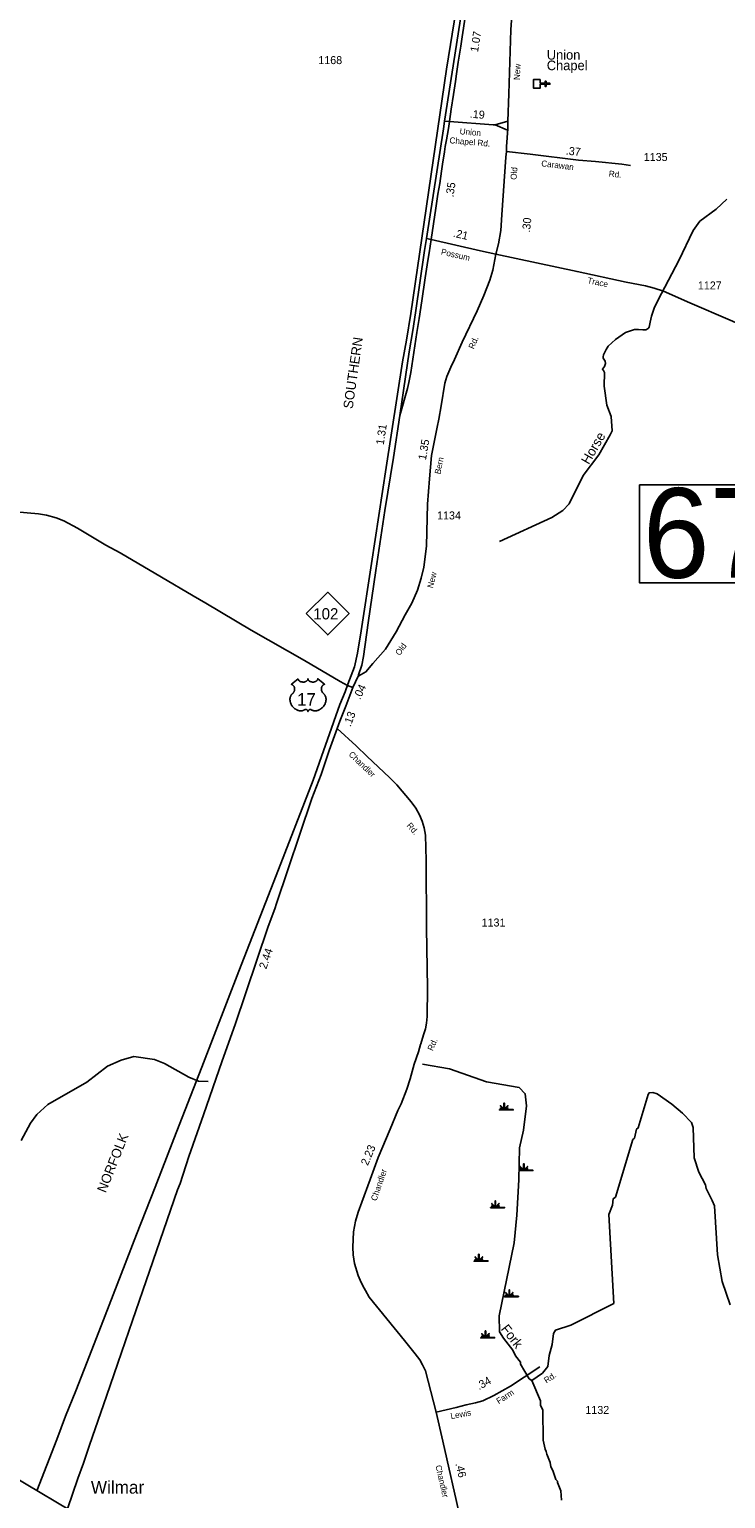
# Model space of a CAD drawing. Extents: x 2532689 to 2764727, y 536648 to 732970.
# Drawn here: x 2552614 to 2563477, y 604102 to 627049 of the extents above; entities that cross this region are included whole.
import ezdxf

# ---------------------------------------------------------------- set-up
doc = ezdxf.new("R2010")
doc.units = 0
for name, color, linetype in [('Exist Boundary Political CountyLine', 7, 'Continuous'), ('Exist Civil Demographics Community Label', 7, 'Continuous'), ('Exist Cultural Church CELL', 7, 'Continuous'), ('Exist Cultural Church Label', 7, 'Continuous'), ('Exist Hydrographic Creek Single Shore', 7, 'Continuous'), ('Exist Hydrographic Creek Single Shore Label', 7, 'Continuous'), ('Exist Hydrographic Swamp CELL', 7, 'Continuous'), ('Exist Railroad Mainline', 7, 'Continuous'), ('Exist Railroad Mainline Label', 7, 'Continuous'), ('Exist Road Primary NC Attributed', 7, 'Continuous'), ('Exist Road Primary NC Shield CELL', 7, 'Continuous'), ('Exist Road Primary NC Shield Number Label', 7, 'Continuous'), ('Exist Road Primary US Attributed', 7, 'Continuous'), ('Exist Road Primary US Divided Attributed', 7, 'Continuous'), ('Exist Road Primary US Mileage Hundredths English Label', 7, 'Continuous'), ('Exist Road Primary US Shield CELL', 7, 'Continuous'), ('Exist Road Primary US Shield Number Label', 7, 'Continuous'), ('Exist Road Secondary Mileage Hundredths English Label', 7, 'Continuous'), ('Exist Road Secondary Structure Standard Bridge Number Label', 7, 'Continuous'), ('Exist Road Secondary Type 20 Attributed', 7, 'Continuous'), ('Exist Road Secondary Type 51 Attributed', 7, 'Continuous'), ('Exist Road Secondary Type 51 Divided Attributed', 7, 'Continuous'), ('Exist Road Secondary Type 51 Label', 7, 'Continuous'), ('Exist Road Secondary Type 51 Number Label', 7, 'Continuous')]:
    doc.layers.add(name, color=color, linetype=linetype)

msp = doc.modelspace()

# ---------------------------------------------------------------- linework, layer by layer
at = {"layer": 'Exist Boundary Political CountyLine'}
msp.add_lwpolyline([(2539489, 612112), (2541484, 610924), (2543090, 609968), (2546865, 607719), (2548776, 606581), (2551142, 605172), (2553489, 603774), (2555345, 602668), (2557351, 601473), (2559512, 600187), (2561378, 599075), (2566102, 596262), (2569405, 594294), (2586179, 584303), (2593549, 579914), (2608947, 570743), (2617220, 563503), (2625601, 556169), (2628092, 553990)], dxfattribs=at)
at = {"layer": 'Exist Cultural Church CELL'}
msp.add_lwpolyline([(2560584, 626264), (2560584, 626207), (2560661, 626207), (2560661, 626239), (2560677, 626239), (2560677, 626207), (2560737, 626207), (2560737, 626191), (2560677, 626191), (2560677, 626159), (2560661, 626159), (2560661, 626191), (2560584, 626191), (2560584, 626133), (2560478, 626133), (2560478, 626264)], close=True, dxfattribs=at)
at = {"layer": 'Exist Hydrographic Creek Single Shore'}
for points in [[(2559949, 619049), (2560766, 619424), (2560939, 619536), (2561037, 619638), (2561253, 620083), (2561498, 620405), (2561674, 620718), (2561706, 620778), (2561694, 621001), (2561623, 621182), (2561584, 621476), (2561585, 621691), (2561574, 621719), (2561555, 621744), (2561587, 621782), (2561601, 621830), (2561598, 621865), (2561566, 621912), (2561569, 621937), (2561571, 621964), (2561614, 622048), (2561645, 622103), (2561759, 622207), (2561917, 622315), (2562055, 622360), (2562118, 622363), (2562184, 622356), (2562232, 622358), (2562268, 622377), (2562282, 622396), (2562302, 622477), (2562319, 622570), (2562366, 622713), (2562477, 622924), (2562746, 623440), (2562970, 623909), (2563076, 624054), (2563330, 624242), (2563494, 624396)], [(2552488, 609696), (2552632, 609965), (2552730, 610100), (2552902, 610255), (2553512, 610608), (2553833, 610854), (2554047, 610951), (2554246, 611005), (2554564, 610959), (2554723, 610896), (2555103, 610685), (2555253, 610622), (2555403, 610615)], [(2560456, 605944), (2560413, 605975), (2560276, 606199), (2560275, 606232), (2560198, 606331), (2560155, 606421), (2560009, 606609), (2559949, 606708), (2559944, 606957), (2560180, 608096), (2560222, 608531), (2560253, 609081), (2560260, 609580), (2560321, 609858), (2560372, 610235), (2560351, 610424), (2560258, 610522), (2559748, 610613), (2559169, 610816), (2558750, 610885)], [(2560456, 605944), (2560620, 606062), (2560701, 606164), (2560723, 606339), (2560770, 606508), (2560791, 606683), (2560824, 606734), (2561064, 606812), (2561732, 607151), (2561655, 608540), (2561710, 608683), (2561725, 608786), (2561758, 608810), (2562032, 609708), (2562057, 609732), (2562087, 609874), (2562112, 609891), (2562268, 610413), (2562284, 610437), (2562343, 610446), (2562410, 610422), (2562638, 610261), (2562807, 610123), (2562944, 609974), (2562970, 609900), (2562988, 609425), (2563059, 609201), (2563163, 609005), (2563172, 608946), (2563267, 608756), (2563302, 608672), (2563351, 607909), (2563425, 607492), (2563549, 607129)], [(2560917, 604078), (2560906, 604225), (2560853, 604351), (2560853, 604374), (2560827, 604400), (2560783, 604542), (2560749, 604600), (2560739, 604665), (2560686, 604798), (2560677, 604840), (2560660, 604872), (2560632, 605012), (2560623, 605481), (2560588, 605562), (2560587, 605628), (2560456, 605944)]]:
    msp.add_lwpolyline(points, dxfattribs=at)
at = {"layer": 'Exist Hydrographic Swamp CELL'}
for points in [[(2559947, 610179), (2559999, 610179), (2560001, 610183), (2559963, 610198), (2559966, 610203), (2560004, 610187), (2560005, 610190), (2559961, 610235), (2559966, 610240), (2560011, 610194), (2560018, 610197), (2560018, 610280), (2560025, 610280), (2560025, 610197), (2560031, 610194), (2560077, 610240), (2560082, 610235), (2560037, 610190), (2560039, 610187), (2560080, 610205), (2560083, 610200), (2560042, 610182), (2560043, 610179), (2560164, 610179), (2560164, 610172), (2559947, 610172)], [(2560254, 609231), (2560306, 609231), (2560308, 609234), (2560270, 609249), (2560273, 609255), (2560311, 609239), (2560312, 609242), (2560268, 609286), (2560273, 609291), (2560318, 609246), (2560325, 609248), (2560325, 609331), (2560332, 609331), (2560332, 609248), (2560338, 609246), (2560384, 609291), (2560389, 609286), (2560344, 609242), (2560346, 609238), (2560387, 609257), (2560390, 609252), (2560349, 609234), (2560350, 609231), (2560471, 609231), (2560471, 609224), (2560254, 609224)], [(2559810, 608651), (2559863, 608651), (2559865, 608655), (2559827, 608669), (2559830, 608675), (2559867, 608659), (2559869, 608662), (2559825, 608706), (2559830, 608711), (2559875, 608666), (2559881, 608668), (2559881, 608751), (2559889, 608751), (2559889, 608668), (2559895, 608666), (2559940, 608711), (2559945, 608706), (2559901, 608662), (2559903, 608658), (2559944, 608677), (2559946, 608672), (2559905, 608654), (2559907, 608651), (2560028, 608651), (2560028, 608644), (2559810, 608644)], [(2559552, 607817), (2559604, 607817), (2559606, 607821), (2559568, 607836), (2559571, 607841), (2559609, 607825), (2559610, 607828), (2559566, 607872), (2559571, 607878), (2559616, 607832), (2559623, 607834), (2559623, 607918), (2559630, 607918), (2559630, 607834), (2559636, 607832), (2559682, 607878), (2559687, 607872), (2559642, 607828), (2559644, 607824), (2559685, 607843), (2559688, 607838), (2559647, 607820), (2559648, 607817), (2559769, 607817), (2559769, 607810), (2559552, 607810)], [(2560027, 607261), (2560080, 607261), (2560082, 607264), (2560044, 607279), (2560047, 607284), (2560084, 607269), (2560086, 607272), (2560042, 607316), (2560047, 607321), (2560092, 607276), (2560098, 607278), (2560098, 607361), (2560106, 607361), (2560105, 607278), (2560112, 607276), (2560157, 607321), (2560162, 607316), (2560118, 607272), (2560120, 607268), (2560161, 607287), (2560163, 607282), (2560122, 607264), (2560124, 607261), (2560245, 607261), (2560245, 607254), (2560027, 607254)], [(2559656, 606619), (2559708, 606619), (2559710, 606623), (2559672, 606638), (2559675, 606643), (2559713, 606627), (2559714, 606630), (2559670, 606675), (2559675, 606680), (2559720, 606634), (2559727, 606637), (2559727, 606720), (2559734, 606720), (2559734, 606637), (2559740, 606634), (2559785, 606680), (2559791, 606675), (2559746, 606630), (2559748, 606627), (2559789, 606645), (2559792, 606640), (2559751, 606622), (2559752, 606619), (2559873, 606619), (2559873, 606612), (2559656, 606612)]]:
    msp.add_lwpolyline(points, close=True, dxfattribs=at)
at = {"layer": 'Exist Railroad Mainline'}
msp.add_lwpolyline([(2552731, 604225), (2553044, 605026), (2553179, 605388), (2553340, 605787), (2553468, 606119), (2553735, 606802), (2554045, 607606), (2554283, 608226), (2554578, 608968), (2554868, 609723), (2555303, 610839), (2555882, 612338), (2556466, 613836), (2557041, 615325), (2557457, 616503), (2557539, 616700), (2557584, 616824), (2557685, 617095), (2557735, 617306), (2557793, 617657), (2557953, 618705), (2558182, 620206), (2558438, 621856), (2558498, 622195), (2558566, 622610), (2559124, 626429), (2559455, 628488)], dxfattribs=at)
at = {"layer": 'Exist Road Primary NC Attributed'}
for points in [[(2552403, 619515), (2552756, 619481), (2552879, 619463), (2553034, 619418), (2553152, 619371), (2553365, 619260), (2553808, 618994), (2554030, 618871), (2554675, 618493), (2555170, 618202), (2555369, 618088), (2556075, 617667), (2556905, 617191), (2557461, 616863), (2557575, 616800)], [(2557575, 616800), (2557660, 616769)]]:
    msp.add_lwpolyline(points, dxfattribs=at)
at = {"layer": 'Exist Road Primary NC Shield CELL'}
msp.add_lwpolyline([(2556935, 617924), (2557268, 618257), (2557601, 617924), (2557268, 617591)], close=True, dxfattribs=at)
at = {"layer": 'Exist Road Primary US Attributed'}
msp.add_line((2557660, 616769), (2557745, 616949), dxfattribs=at)
for points in [[(2557745, 616949), (2557751, 616970), (2557799, 617119), (2557828, 617253), (2557898, 617778), (2558020, 618596), (2558162, 619533), (2558293, 620364), (2558395, 621018), (2558395, 621018)], [(2557415, 616128), (2557460, 616244), (2557549, 616478), (2557660, 616769)], [(2553208, 603941), (2553370, 604418), (2553458, 604656), (2553552, 604935), (2553816, 605700), (2553995, 606216), (2554221, 606881), (2554487, 607652), (2554923, 608925), (2554966, 609023), (2555104, 609444), (2555329, 610097), (2555622, 610940), (2555823, 611508), (2556335, 613022), (2556447, 613331), (2556464, 613382), (2557023, 615034), (2557168, 615414), (2557290, 615784), (2557415, 616128)]]:
    msp.add_lwpolyline(points, dxfattribs=at)
at = {"layer": 'Exist Road Primary US Divided Attributed'}
for points in [[(2559093, 625618), (2559329, 627145), (2559682, 629461), (2559748, 629889), (2559902, 630931), (2559956, 631259)], [(2559169, 625612), (2559193, 625805), (2559230, 626033), (2559260, 626236), (2559278, 626353), (2559306, 626537), (2559330, 626695), (2559345, 626787), (2559367, 626935), (2559413, 627238)], [(2558808, 623783), (2559074, 625498), (2559093, 625618)], [(2558882, 623768), (2558918, 624011), (2558956, 624256), (2558989, 624475), (2559017, 624643), (2559046, 624836), (2559060, 624943), (2559091, 625135), (2559103, 625222), (2559121, 625325), (2559152, 625499), (2559169, 625612)], [(2558395, 621018), (2558538, 622013), (2558596, 622344), (2558636, 622624), (2558781, 623596), (2558808, 623783)], [(2558395, 621018), (2558514, 621442), (2558535, 621536), (2558566, 621692), (2558595, 621898), (2558627, 622107), (2558659, 622314), (2558695, 622536), (2558737, 622812), (2558790, 623167), (2558832, 623439), (2558850, 623559), (2558882, 623768)]]:
    msp.add_lwpolyline(points, dxfattribs=at)
at = {"layer": 'Exist Road Primary US Shield CELL'}
msp.add_lwpolyline([(2556809, 616906), (2556809, 616902), (2556810, 616896), (2556811, 616894), (2556814, 616889), (2556818, 616882), (2556823, 616876), (2556830, 616871), (2556834, 616869), (2556841, 616865), (2556849, 616861), (2556858, 616859), (2556868, 616857), (2556878, 616856), (2556888, 616855), (2556899, 616856), (2556911, 616858), (2556917, 616860), (2556923, 616862), (2556929, 616864), (2556935, 616868), (2556940, 616871), (2556944, 616874), (2556950, 616879), (2556954, 616885), (2556956, 616888), (2556958, 616891), (2556960, 616898), (2556961, 616900), (2556961, 616906), (2556961, 616901), (2556962, 616898), (2556963, 616895), (2556964, 616892), (2556966, 616887), (2556969, 616884), (2556973, 616878), (2556976, 616875), (2556979, 616873), (2556986, 616868), (2556995, 616864), (2556999, 616862), (2557003, 616861), (2557009, 616859), (2557014, 616858), (2557020, 616857), (2557025, 616856), (2557031, 616855), (2557036, 616855), (2557042, 616855), (2557047, 616856), (2557052, 616856), (2557058, 616857), (2557063, 616858), (2557070, 616860), (2557075, 616862), (2557081, 616864), (2557087, 616868), (2557092, 616871), (2557096, 616874), (2557101, 616879), (2557105, 616884), (2557108, 616887), (2557110, 616891), (2557111, 616895), (2557113, 616899), (2557113, 616903), (2557113, 616906), (2557219, 616822), (2557217, 616821), (2557211, 616818), (2557207, 616815), (2557199, 616810), (2557196, 616807), (2557193, 616804), (2557190, 616801), (2557188, 616798), (2557184, 616794), (2557182, 616790), (2557179, 616785), (2557177, 616781), (2557174, 616772), (2557172, 616767), (2557171, 616762), (2557170, 616753), (2557170, 616748), (2557170, 616744), (2557170, 616739), (2557170, 616735), (2557171, 616730), (2557172, 616726), (2557173, 616721), (2557175, 616715), (2557177, 616709), (2557182, 616700), (2557188, 616690), (2557193, 616685), (2557197, 616681), (2557204, 616675), (2557207, 616672), (2557212, 616668), (2557218, 616660), (2557221, 616657), (2557224, 616652), (2557226, 616648), (2557229, 616644), (2557231, 616640), (2557234, 616631), (2557237, 616622), (2557238, 616617), (2557240, 616607), (2557241, 616602), (2557242, 616591), (2557242, 616579), (2557241, 616567), (2557239, 616554), (2557237, 616546), (2557234, 616536), (2557231, 616528), (2557227, 616516), (2557222, 616507), (2557217, 616497), (2557213, 616490), (2557208, 616484), (2557203, 616476), (2557196, 616468), (2557188, 616459), (2557182, 616453), (2557174, 616446), (2557169, 616441), (2557162, 616436), (2557152, 616430), (2557142, 616424), (2557134, 616420), (2557127, 616417), (2557117, 616413), (2557102, 616409), (2557096, 616408), (2557089, 616407), (2557083, 616406), (2557077, 616405), (2557068, 616405), (2557060, 616406), (2557052, 616407), (2557044, 616409), (2557036, 616411), (2557028, 616414), (2557020, 616418), (2557007, 616427), (2557003, 616429), (2557001, 616429), (2556996, 616429), (2556991, 616428), (2556986, 616426), (2556984, 616425), (2556980, 616422), (2556977, 616420), (2556973, 616416), (2556970, 616414), (2556969, 616411), (2556965, 616405), (2556964, 616403), (2556962, 616399), (2556961, 616394), (2556959, 616401), (2556957, 616405), (2556955, 616409), (2556953, 616412), (2556949, 616416), (2556946, 616419), (2556942, 616423), (2556937, 616425), (2556934, 616427), (2556931, 616428), (2556927, 616429), (2556924, 616429), (2556921, 616429), (2556918, 616429), (2556913, 616425), (2556908, 616422), (2556903, 616419), (2556898, 616416), (2556893, 616414), (2556888, 616412), (2556882, 616410), (2556875, 616408), (2556869, 616407), (2556863, 616406), (2556857, 616405), (2556851, 616405), (2556845, 616405), (2556839, 616406), (2556833, 616406), (2556825, 616407), (2556818, 616409), (2556811, 616411), (2556804, 616413), (2556796, 616416), (2556786, 616420), (2556780, 616424), (2556769, 616430), (2556757, 616438), (2556747, 616446), (2556740, 616452), (2556730, 616462), (2556724, 616469), (2556715, 616481), (2556709, 616490), (2556705, 616496), (2556700, 616507), (2556697, 616513), (2556693, 616522), (2556689, 616531), (2556687, 616539), (2556685, 616544), (2556683, 616554), (2556682, 616560), (2556681, 616569), (2556680, 616578), (2556680, 616587), (2556680, 616594), (2556681, 616602), (2556683, 616611), (2556684, 616619), (2556686, 616624), (2556688, 616631), (2556691, 616638), (2556695, 616645), (2556698, 616651), (2556702, 616657), (2556706, 616663), (2556712, 616669), (2556717, 616674), (2556722, 616678), (2556729, 616684), (2556732, 616688), (2556736, 616693), (2556739, 616698), (2556741, 616702), (2556744, 616708), (2556746, 616713), (2556749, 616720), (2556750, 616725), (2556751, 616731), (2556752, 616738), (2556752, 616745), (2556752, 616751), (2556751, 616759), (2556750, 616766), (2556748, 616772), (2556746, 616779), (2556743, 616784), (2556739, 616791), (2556735, 616798), (2556730, 616803), (2556725, 616808), (2556721, 616811), (2556717, 616814), (2556711, 616817), (2556706, 616820), (2556703, 616821)], close=True, dxfattribs=at)
at = {"layer": 'Exist Road Secondary Structure Standard Bridge Number Label'}
msp.add_lwpolyline([(2562135, 619935), (2564712, 619935), (2564712, 618405), (2562135, 618405)], close=True, dxfattribs=at)
at = {"layer": 'Exist Road Secondary Type 20 Attributed'}
msp.add_lwpolyline([(2558960, 605451), (2559274, 605527), (2559428, 605568), (2559577, 605595), (2559688, 605631), (2559859, 605713), (2560120, 605858), (2560333, 605998), (2560580, 606161)], dxfattribs=at)
at = {"layer": 'Exist Road Secondary Type 51 Attributed'}
msp.add_line((2558882, 623768), (2558808, 623783), dxfattribs=at)
for points in [[(2560081, 625615), (2560094, 626043), (2560126, 627043), (2560145, 627337), (2560170, 627959), (2560167, 628059), (2560153, 628147), (2560137, 628342), (2560128, 628438), (2560113, 628699), (2560124, 628814), (2560140, 628994), (2560151, 629098), (2560181, 629417), (2560177, 629474), (2560222, 629909), (2560261, 630550), (2560337, 630908), (2560369, 631077), (2560387, 631172)], [(2559093, 625618), (2559169, 625612)], [(2559169, 625612), (2559851, 625559), (2559879, 625557), (2559881, 625556)], [(2560078, 625498), (2560081, 625615)], [(2560056, 625144), (2560060, 625219), (2560078, 625498)], [(2559890, 623538), (2559936, 623698), (2559969, 623907), (2559987, 624152), (2560048, 625055), (2560056, 625144)], [(2560056, 625144), (2560430, 625098), (2561184, 625005), (2561448, 624985), (2561859, 624942), (2561991, 624923)], [(2559890, 623538), (2559652, 623593), (2558882, 623768)], [(2557745, 616949), (2557789, 616972), (2557864, 617014), (2557975, 617146), (2558170, 617369), (2558339, 617639), (2558478, 617903), (2558579, 618090), (2558667, 618290), (2558727, 618477), (2558770, 618652), (2558785, 618768), (2558810, 618982), (2558827, 619636), (2558856, 620031), (2558889, 620393), (2558975, 620835), (2559001, 620959), (2559037, 621169), (2559098, 621524), (2559127, 621628), (2559188, 621776), (2559246, 621895), (2559368, 622163), (2559601, 622651), (2559704, 622891), (2559798, 623134), (2559843, 623289), (2559890, 623538)], [(2568438, 621427), (2567962, 621436), (2567357, 621448), (2566914, 621452), (2566419, 621460), (2566075, 621474), (2565968, 621487), (2565900, 621502), (2565716, 621565), (2565507, 621652), (2564415, 622129), (2563547, 622505), (2562917, 622777), (2562508, 622960), (2562364, 623007), (2562228, 623042), (2561924, 623103), (2561159, 623266), (2559890, 623538)], [(2557415, 616128), (2557714, 615857), (2557886, 615693), (2558234, 615365), (2558348, 615248), (2558572, 614986), (2558643, 614885), (2558702, 614780), (2558742, 614684), (2558775, 614581), (2558793, 614464), (2558805, 614069), (2558811, 613018), (2558825, 612073), (2558819, 611630), (2558808, 611528), (2558792, 611440), (2558764, 611346), (2558720, 611206), (2558714, 611192), (2558683, 611081), (2558619, 610888), (2558553, 610657), (2558502, 610498), (2558413, 610267), (2558364, 610162), (2558244, 609870), (2558054, 609427), (2557933, 609086), (2557802, 608733), (2557743, 608573), (2557704, 608437), (2557672, 608266), (2557660, 608030), (2557666, 607909), (2557688, 607776), (2557744, 607585), (2557790, 607478), (2557837, 607389), (2557858, 607353), (2557917, 607248), (2558466, 606571), (2558633, 606363), (2558704, 606270), (2558750, 606192), (2558793, 606095), (2558960, 605451)], [(2558960, 605451), (2559065, 604997), (2559339, 603782), (2559361, 603566), (2559351, 603384), (2559330, 603080)]]:
    msp.add_lwpolyline(points, dxfattribs=at)
at = {"layer": 'Exist Road Secondary Type 51 Divided Attributed'}
msp.add_line((2559881, 625556), (2560081, 625615), dxfattribs=at)
msp.add_lwpolyline([(2559881, 625556), (2560076, 625473)], dxfattribs=at)

# ---------------------------------------------------------------- texts
at = {"layer": 'Exist Civil Demographics Community Label'}
msp.add_text('Wilmar', height=200, dxfattribs=at).set_placement((2553573, 604179))
at = {"layer": 'Exist Cultural Church Label'}
for s, p in [('Union', (2560687, 626577)), ('Chapel', (2560687, 626412))]:
    msp.add_text(s, height=150, dxfattribs=at).set_placement(p)
at = {"layer": 'Exist Hydrographic Creek Single Shore Label'}
for s, rotation, p in [('Horse', 60.0294, (2561343, 620242)), ('Fork', 307.8577, (2559962, 606749))]:
    msp.add_text(s, height=150, rotation=rotation, dxfattribs=at).set_placement(p)
at = {"layer": 'Exist Railroad Mainline Label'}
for s, rotation, p in [('SOUTHERN', 81.8619, (2557658, 621117)), ('NORFOLK', 68.2688, (2553804, 608868))]:
    msp.add_text(s, height=150, rotation=rotation, dxfattribs=at).set_placement(p)
at = {"layer": 'Exist Road Primary NC Shield Number Label'}
msp.add_text('102', height=175, dxfattribs=at).set_placement((2557044, 617834))
at = {"layer": 'Exist Road Primary US Mileage Hundredths English Label'}
for s, rotation, p in [('1.07', 80.7675, (2559613, 626688)), ('.35', 81.202, (2559229, 624423)), ('1.31', 81.2511, (2558142, 620553)), ('.04', 64.727, (2557774, 616572)), ('.13', 69.3027, (2557625, 616149)), ('2.44', 71.2989, (2556310, 612364))]:
    msp.add_text(s, height=125, rotation=rotation, dxfattribs=at).set_placement(p)
at = {"layer": 'Exist Road Primary US Shield Number Label'}
msp.add_text('17', height=195, dxfattribs=at).set_placement((2556792, 616487))
at = {"layer": 'Exist Road Secondary Mileage Hundredths English Label'}
for s, rotation, p in [('.19', 355.0129, (2559482, 625671)), ('.37', 354.14, (2560979, 625095)), ('.30', 84.2735, (2560424, 623872)), ('.21', 347.0377, (2559218, 623812)), ('1.35', 79.803, (2558800, 620315)), ('2.23', 67.3152, (2557894, 609294)), ('.34', 28.9916, (2559629, 605794)), ('.46', 283.0487, (2559261, 604646))]:
    msp.add_text(s, height=125, rotation=rotation, dxfattribs=at).set_placement(p)
at = {"layer": 'Exist Road Secondary Structure Standard Bridge Number Label'}
msp.add_text('67', height=1400, dxfattribs=at).set_placement((2562185, 618484))
at = {"layer": 'Exist Road Secondary Type 51 Label'}
for s, rotation, p in [('New', 87.2786, (2560266, 626256)), ('Chapel Rd.', 355.0129, (2559166, 625271)), ('Union ', 355.0129, (2559325, 625412)), ('Old', 85.3149, (2560214, 624697)), ('Carawan', 352.9709, (2560597, 624912)), ('Rd.', 354.14, (2561651, 624750)), ('Possum', 347.0378, (2559030, 623534)), ('Trace', 348.2497, (2561314, 623086)), ('Rd.', 66.9799, (2559548, 622048)), ('Bern', 78.3686, (2559027, 620095)), ('New', 76.3276, (2558911, 618315)), ('Old', 54.4008, (2558392, 617260)), ('Chandler', 316.4746, (2557587, 615714)), ('Rd.', 310.0012, (2558494, 614611)), ('Rd.', 65.7494, (2558907, 611086)), ('Chandler', 71.1731, (2558028, 608743)), ('Rd.', 33.4304, (2560681, 605898)), ('Farm', 33.3288, (2559938, 605574)), ('Lewis', 10.4442, (2559194, 605343)), ('Chandler', 283.0487, (2558948, 604613))]:
    msp.add_text(s, height=95, rotation=rotation, dxfattribs=at).set_placement(p)
at = {"layer": 'Exist Road Secondary Type 51 Number Label'}
for s, p in [('1168', (2557122, 626507)), ('1135', (2562200, 624994)), ('1127', (2563044, 622987)), ('1134', (2558975, 619395)), ('1131', (2559670, 613037)), ('1132', (2561289, 605424))]:
    msp.add_text(s, height=125, dxfattribs=at).set_placement(p)

doc.saveas('drawing.dxf')
